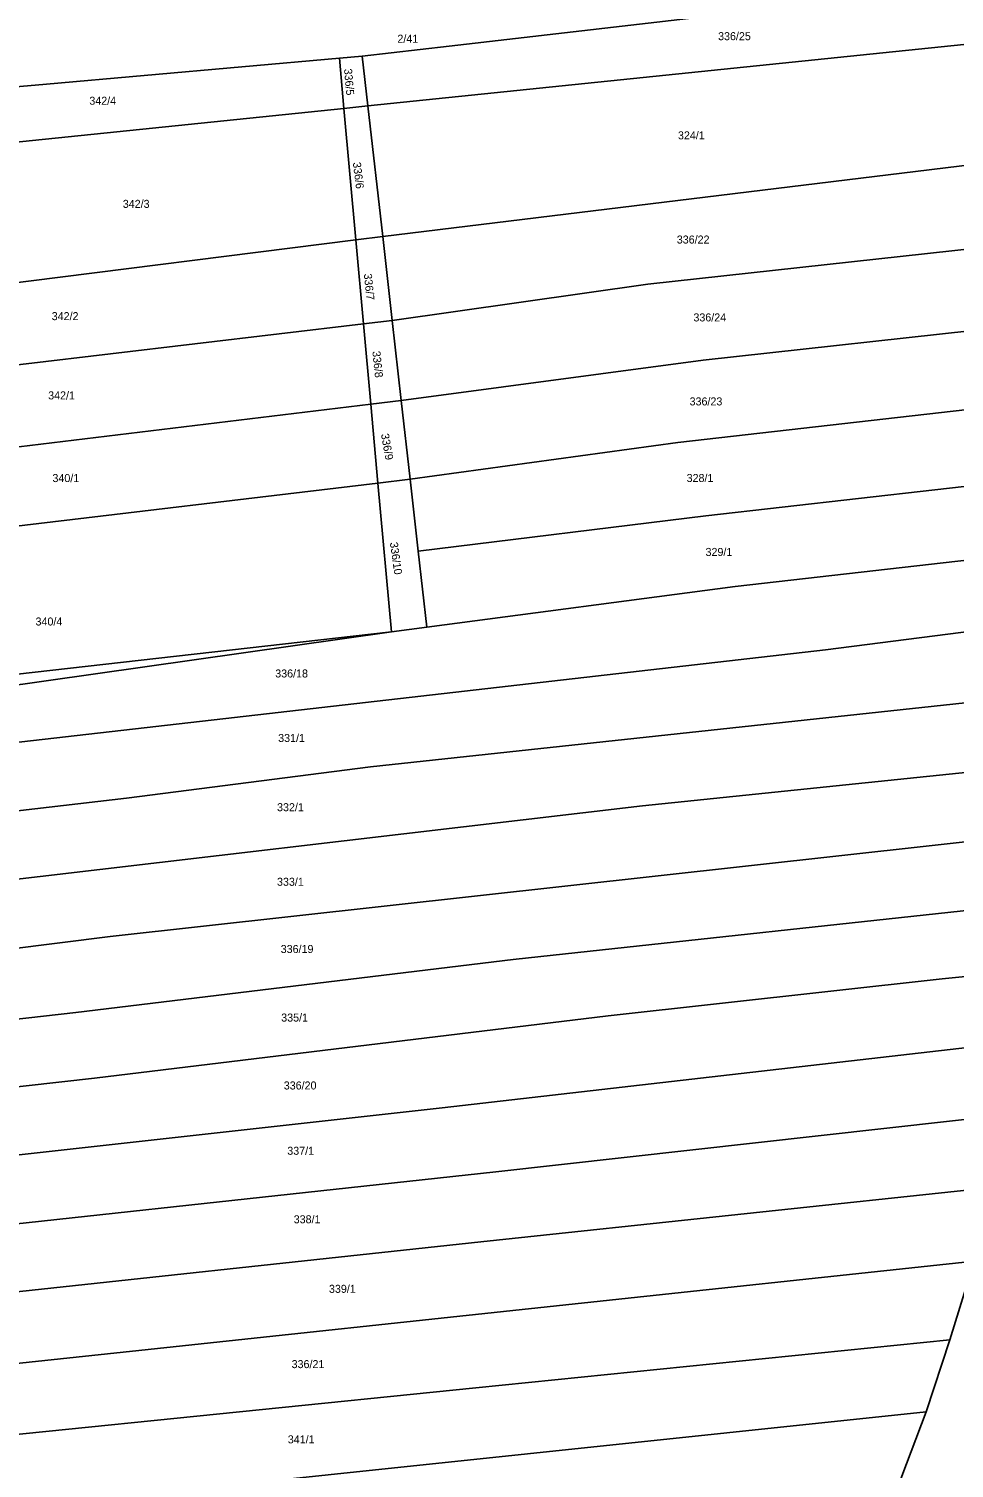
# Model space of a CAD drawing. Extents: x -747333 to -743907, y -1134120 to -1130051.
# Drawn here: x -746082.4 to -745885.9, y -1131946.1 to -1131640.4 of the extents above; entities that cross this region are included whole.
import ezdxf

# ---------------------------------------------------------------- set-up
doc = ezdxf.new("R2010")
doc.units = 0
doc.layers.add('Hranice parcel', color=7, linetype='Continuous')
doc.layers.add('Parcelní čísla', color=7, linetype='Continuous')

msp = doc.modelspace()

# ---------------------------------------------------------------- linework, layer by layer
at = {"layer": 'Hranice parcel'}
for p, q in [((-745876.7, -1131642.95), (-746010.34, -1131656.73)), ((-746016.41, -1131646.56), (-746011.54, -1131646.14)), ((-746016.41, -1131646.56), (-746015.44, -1131657.26)), ((-746010.34, -1131656.73), (-746011.54, -1131646.14)), ((-746015.44, -1131657.26), (-746104.37, -1131666.43)), ((-746015.44, -1131657.26), (-746010.34, -1131656.73)), ((-746015.44, -1131657.26), (-746012.9, -1131685.16)), ((-746007.21, -1131684.44), (-746010.34, -1131656.73)), ((-746007.21, -1131684.44), (-745875.94, -1131668.46)), ((-746012.9, -1131685.16), (-746119.9, -1131698.71)), ((-746012.9, -1131685.16), (-746007.21, -1131684.44)), ((-746012.9, -1131685.16), (-746011.28, -1131703.02)), ((-746005.19, -1131702.3), (-746007.21, -1131684.44)), ((-746011.28, -1131703.02), (-746005.19, -1131702.3)), ((-746009.74, -1131720.07), (-746011.28, -1131703.02)), ((-746003.27, -1131719.29), (-746005.19, -1131702.3)), ((-746009.74, -1131720.07), (-746123.47, -1131733.84)), ((-746009.74, -1131720.07), (-746003.27, -1131719.29)), ((-746008.22, -1131736.82), (-746009.74, -1131720.07)), ((-746001.38, -1131736), (-746003.27, -1131719.29)), ((-746134.41, -1131751.93), (-746008.22, -1131736.82)), ((-746008.22, -1131736.82), (-746001.38, -1131736)), ((-746005.35, -1131768.4), (-746008.22, -1131736.82)), ((-745999.66, -1131751.26), (-746001.38, -1131736)), ((-745997.83, -1131767.45), (-745999.66, -1131751.26)), ((-746157.45, -1131789.98), (-746005.35, -1131768.4)), ((-746154.67, -1131785.39), (-746005.35, -1131768.4)), ((-746005.35, -1131768.4), (-745997.83, -1131767.45)), ((-745881.66, -1131902.09), (-745886.79, -1131918.79)), ((-745886.79, -1131918.79), (-745891.79, -1131934.06)), ((-745898.21, -1131950.9), (-745891.79, -1131934.06))]:
    msp.add_line(p, q, dxfattribs=at)
for points in [[(-746011.54, -1131646.14), (-745993.09, -1131644.03), (-745877.4, -1131630.6)], [(-746090.01, -1131653.11), (-746078.61, -1131652.1), (-746016.41, -1131646.56)], [(-746005.19, -1131702.3), (-745950.93, -1131694.59), (-745875.37, -1131686.32)], [(-746011.28, -1131703.02), (-746082.88, -1131711.52), (-746090.83, -1131712.46), (-746118.38, -1131715.73)], [(-745874.81, -1131703.67), (-745939.15, -1131710.71), (-746003.27, -1131719.29)], [(-745874.28, -1131720.25), (-745944.57, -1131728.25), (-746001.38, -1131736)], [(-745999.66, -1131751.26), (-745938.57, -1131743.81), (-745873.76, -1131736.42)], [(-745997.83, -1131767.45), (-745932.36, -1131758.79), (-745873.31, -1131752.1)], [(-745872.82, -1131767.1), (-745913.22, -1131772.23), (-746038.67, -1131786.65), (-746091.32, -1131792.64), (-746145.12, -1131798.49), (-746163.91, -1131800.98)], [(-746173.02, -1131816.46), (-746145.54, -1131813.2), (-746104.87, -1131808.78), (-746061.62, -1131803.78), (-746009.82, -1131797.07), (-745872.32, -1131782.29)], [(-746182.24, -1131832.12), (-746144.56, -1131828.9), (-746105.32, -1131823.34), (-745952.05, -1131805.35), (-745871.83, -1131797.13)], [(-746191.35, -1131847.6), (-746119.75, -1131839.99), (-746065.09, -1131833.14), (-745871.36, -1131811.65)], [(-745870.88, -1131826.3), (-745979.48, -1131837.99), (-746072.36, -1131849.26), (-746138, -1131856.68), (-746200.63, -1131862.93)], [(-746210.48, -1131879.13), (-746068.37, -1131863.25), (-745959.35, -1131849.97), (-745888.43, -1131842.13), (-745871.39, -1131840.43)], [(-746217.97, -1131893.97), (-746182.66, -1131890.66), (-746128.44, -1131884.38), (-745994.6, -1131869.54), (-745871.94, -1131855.43)], [(-746224.39, -1131909.81), (-746154.83, -1131902.38), (-746129.29, -1131898.95), (-745983.18, -1131883.12), (-745872.95, -1131870.82)], [(-746215.18, -1131922.7), (-746100.74, -1131910.33), (-745986.39, -1131897.96), (-745877.23, -1131886.38)], [(-745881.66, -1131902.09), (-746058.97, -1131921.07), (-746214.71, -1131937.61)], [(-746214.24, -1131952.56), (-746172.98, -1131949.05), (-746087.79, -1131939.2), (-745987.44, -1131929), (-745886.79, -1131918.79)], [(-745891.79, -1131934.06), (-746061.11, -1131951.9), (-746178.97, -1131965.04), (-746213.8, -1131966.46)]]:
    msp.add_lwpolyline(points, dxfattribs=at)

# ---------------------------------------------------------------- texts
at = {"layer": 'Parcelní čísla'}
for s, p in [('2/41', (-746004.09, -1131643.31)), ('336/25', (-745936, -1131642.77)), ('342/4', (-746069.5, -1131656.48)), ('324/1', (-745944.52, -1131663.83)), ('342/3', (-746062.4, -1131678.38)), ('336/22', (-745944.77, -1131685.96)), ('342/2', (-746077.49, -1131702.23)), ('336/24', (-745941.24, -1131702.5)), ('342/1', (-746078.24, -1131719.06)), ('336/23', (-745942.05, -1131720.34)), ('340/1', (-746077.33, -1131736.62)), ('328/1', (-745942.68, -1131736.6)), ('329/1', (-745938.66, -1131752.31)), ('340/4', (-746080.92, -1131767.08)), ('336/18', (-746030.03, -1131778.12)), ('331/1', (-746029.41, -1131791.82)), ('332/1', (-746029.64, -1131806.52)), ('333/1', (-746029.65, -1131822.36)), ('336/19', (-746028.87, -1131836.64)), ('335/1', (-746028.76, -1131851.2)), ('336/20', (-746028.22, -1131865.62)), ('337/1', (-746027.47, -1131879.49)), ('338/1', (-746026.11, -1131894.04)), ('339/1', (-746018.62, -1131908.81)), ('336/21', (-746026.55, -1131924.8)), ('341/1', (-746027.36, -1131940.78))]:
    msp.add_text(s, height=1.7, dxfattribs=at).set_placement(p)
for s, rotation, p in [('336/5', 275, (-746015.426, -1131648.884)), ('336/6', 277, (-746013.553, -1131668.773)), ('336/7', 276, (-746011.225, -1131692.408)), ('336/8', 276, (-746009.415, -1131708.868)), ('336/9', 280, (-746007.587, -1131726.457)), ('336/10', 278, (-746005.691, -1131749.488))]:
    msp.add_text(s, height=1.7, rotation=rotation, dxfattribs=at).set_placement(p)

doc.saveas('drawing.dxf')
